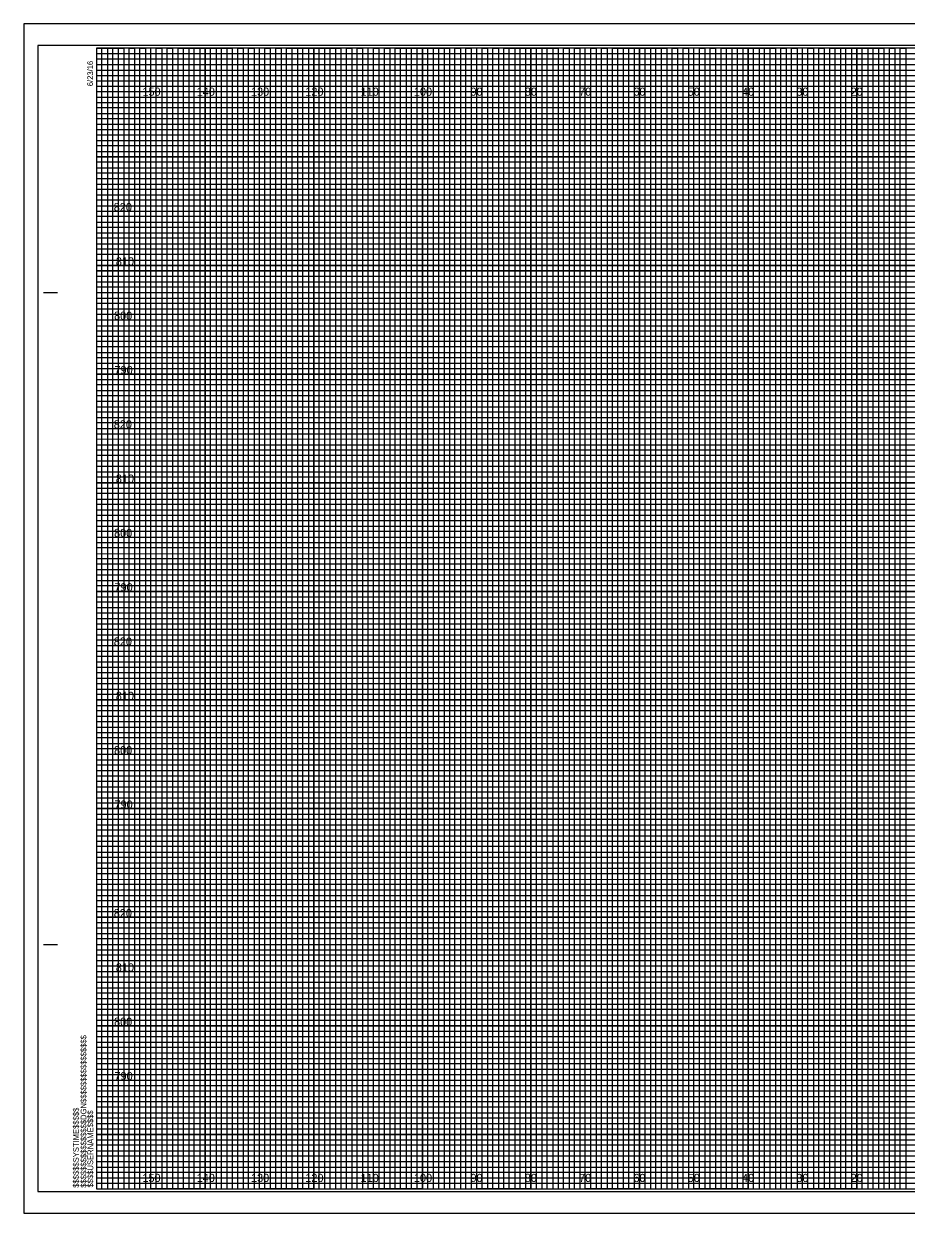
# Model space of a CAD drawing. Extents: x -13 to 323, y -4 to 214.
# Drawn here: x -13.4 to 149.1, y -4.5 to 214.5 of the extents above; entities that cross this region are included whole.
import ezdxf

# ---------------------------------------------------------------- set-up
doc = ezdxf.new("R2010")
doc.units = 0
for name, color, linetype in [('Exist Cross Section Cell', 7, 'Continuous'), ('Exist XS Ground Line', 7, 'Continuous'), ('Prop CMT Conc Surface', 7, 'Continuous'), ('Prop CMT Pvmt Course 1', 7, 'Continuous'), ('Prop CMT Pvmt Course 1 CG', 7, 'Continuous'), ('Prop CMT Pvmt Course 2', 7, 'Continuous'), ('Prop CMT Pvmt Course 3', 7, 'Continuous'), ('Prop CMT Pvmt Surface', 7, 'Continuous'), ('Prop CMT Subgrade Earthwork', 7, 'Continuous'), ('Scratch_Level_4', 7, 'Continuous'), ('Scratch_Level_7', 7, 'Continuous')]:
    doc.layers.add(name, color=color, linetype=linetype)

msp = doc.modelspace()

# ---------------------------------------------------------------- linework, layer by layer
at = {"layer": 'Exist XS Ground Line'}
for p, q in [((10, 210), (0, 210)), ((10, 0), (10, 210)), ((30, 210), (20, 210)), ((20, 210), (20, 0)), ((30, 0), (30, 210)), ((50, 210), (40, 210)), ((40, 210), (40, 0)), ((50, 0), (50, 210)), ((70, 210), (60, 210)), ((60, 210), (60, 0)), ((70, 0), (70, 210)), ((90, 210), (80, 210)), ((80, 210), (80, 0)), ((90, 0), (90, 210)), ((110, 210), (100, 210)), ((100, 210), (100, 0)), ((110, 0), (110, 210)), ((130, 210), (120, 210)), ((120, 210), (120, 0)), ((130, 0), (130, 210)), ((150, 210), (140, 210)), ((140, 210), (140, 0)), ((20, 0), (10, 0)), ((40, 0), (30, 0)), ((60, 0), (50, 0)), ((80, 0), (70, 0)), ((100, 0), (90, 0)), ((120, 0), (110, 0)), ((140, 0), (130, 0))]:
    msp.add_line(p, q, dxfattribs=at)
for points in [[(0, 200), (320, 200), (320, 190), (0, 190)], [(0, 180), (320, 180), (320, 170), (0, 170)], [(0, 160), (320, 160), (320, 150), (0, 150)], [(0, 140), (320, 140), (320, 130), (0, 130)], [(0, 120), (320, 120), (320, 110), (0, 110)], [(0, 100), (320, 100), (320, 90), (0, 90)], [(0, 80), (320, 80), (320, 70), (0, 70)], [(0, 60), (320, 60), (320, 50), (0, 50)], [(0, 40), (320, 40), (320, 30), (0, 30)], [(0, 20), (320, 20), (320, 10), (0, 10)]]:
    msp.add_lwpolyline(points, dxfattribs=at)
at = {"layer": 'Prop CMT Conc Surface'}
for p, q in [((323.3, 214.5), (-13.4, 214.5)), ((-13.4, 214.5), (-13.4, -4.5)), ((-13.4, -4.5), (323.3, -4.5))]:
    msp.add_line(p, q, dxfattribs=at)
at = {"layer": 'Prop CMT Pvmt Course 1'}
for p, q in [((10, 0), (10, 210)), ((20, 0), (20, 210)), ((30, 0), (30, 210)), ((40, 0), (40, 210)), ((50, 0), (50, 210)), ((60, 0), (60, 210)), ((70, 0), (70, 210)), ((80, 0), (80, 210)), ((90, 0), (90, 210)), ((100, 0), (100, 210)), ((110, 0), (110, 210)), ((120, 0), (120, 210)), ((130, 0), (130, 210)), ((140, 0), (140, 210)), ((0, 200), (320, 200)), ((0, 190), (320, 190)), ((0, 180), (320, 180)), ((0, 170), (320, 170)), ((0, 160), (320, 160)), ((0, 150), (320, 150)), ((0, 140), (320, 140)), ((0, 130), (320, 130)), ((0, 120), (320, 120)), ((0, 110), (320, 110)), ((0, 100), (320, 100)), ((0, 90), (320, 90)), ((0, 80), (320, 80)), ((0, 70), (320, 70)), ((0, 60), (320, 60)), ((0, 50), (320, 50)), ((0, 40), (320, 40)), ((0, 30), (320, 30)), ((0, 20), (320, 20)), ((0, 10), (320, 10))]:
    msp.add_line(p, q, dxfattribs=at)
at = {"layer": 'Prop CMT Pvmt Course 1 CG'}
msp.add_lwpolyline([(-10.8, -0.5), (322.4, -0.5), (322.4, 210.5), (-10.8, 210.5)], close=True, dxfattribs=at)
at = {"layer": 'Prop CMT Pvmt Course 2'}
for p, q in [((-9.8, 165), (-7.3, 165)), ((-9.7, 165), (-7.2, 165)), ((-9.8, 45), (-7.3, 45)), ((-9.7, 45), (-7.2, 45)), ((0, 0), (0, 0)), ((0, 0), (0, 0)), ((0, 0), (0, 0)), ((0, 0), (0, 0)), ((0, 0), (0, 0)), ((0, 0), (0, 0)), ((0, 0), (0, 0))]:
    msp.add_line(p, q, dxfattribs=at)
msp.add_lwpolyline([(320, 210), (0, 210), (0, 0), (320, 0)], close=True, dxfattribs=at)
at = {"layer": 'Prop CMT Pvmt Course 3'}
for points in [[(0, 0), (1, 0), (1, 210), (2, 210), (2, 0)], [(2, 0), (3, 0), (3, 210), (4, 210), (4, 0)], [(5, 0), (6, 0), (6, 210), (7, 210), (7, 0)], [(7, 0), (8, 0), (8, 210), (9, 210), (9, 0)], [(10, 0), (11, 0), (11, 210), (12, 210), (12, 0)], [(12, 0), (13, 0), (13, 210), (14, 210), (14, 0)], [(15, 0), (16, 0), (16, 210), (17, 210), (17, 0)], [(17, 0), (18, 0), (18, 210), (19, 210), (19, 0)], [(20, 0), (21, 0), (21, 210), (22, 210), (22, 0)], [(22, 0), (23, 0), (23, 210), (24, 210), (24, 0)], [(25, 0), (26, 0), (26, 210), (27, 210), (27, 0)], [(27, 0), (28, 0), (28, 210), (29, 210), (29, 0)], [(30, 0), (31, 0), (31, 210), (32, 210), (32, 0)], [(32, 0), (33, 0), (33, 210), (34, 210), (34, 0)], [(35, 0), (36, 0), (36, 210), (37, 210), (37, 0)], [(37, 0), (38, 0), (38, 210), (39, 210), (39, 0)], [(40, 0), (41, 0), (41, 210), (42, 210), (42, 0)], [(42, 0), (43, 0), (43, 210), (44, 210), (44, 0)], [(45, 0), (46, 0), (46, 210), (47, 210), (47, 0)], [(47, 0), (48, 0), (48, 210), (49, 210), (49, 0)], [(50, 0), (51, 0), (51, 210), (52, 210), (52, 0)], [(52, 0), (53, 0), (53, 210), (54, 210), (54, 0)], [(55, 0), (56, 0), (56, 210), (57, 210), (57, 0)], [(57, 0), (58, 0), (58, 210), (59, 210), (59, 0)], [(60, 0), (61, 0), (61, 210), (62, 210), (62, 0)], [(62, 0), (63, 0), (63, 210), (64, 210), (64, 0)], [(65, 0), (66, 0), (66, 210), (67, 210), (67, 0)], [(67, 0), (68, 0), (68, 210), (69, 210), (69, 0)], [(70, 0), (71, 0), (71, 210), (72, 210), (72, 0)], [(72, 0), (73, 0), (73, 210), (74, 210), (74, 0)], [(75, 0), (76, 0), (76, 210), (77, 210), (77, 0)], [(77, 0), (78, 0), (78, 210), (79, 210), (79, 0)], [(80, 0), (81, 0), (81, 210), (82, 210), (82, 0)], [(82, 0), (83, 0), (83, 210), (84, 210), (84, 0)], [(85, 0), (86, 0), (86, 210), (87, 210), (87, 0)], [(87, 0), (88, 0), (88, 210), (89, 210), (89, 0)], [(90, 0), (91, 0), (91, 210), (92, 210), (92, 0)], [(92, 0), (93, 0), (93, 210), (94, 210), (94, 0)], [(95, 0), (96, 0), (96, 210), (97, 210), (97, 0)], [(97, 0), (98, 0), (98, 210), (99, 210), (99, 0)], [(100, 0), (101, 0), (101, 210), (102, 210), (102, 0)], [(102, 0), (103, 0), (103, 210), (104, 210), (104, 0)], [(105, 0), (106, 0), (106, 210), (107, 210), (107, 0)], [(107, 0), (108, 0), (108, 210), (109, 210), (109, 0)], [(110, 0), (111, 0), (111, 210), (112, 210), (112, 0)], [(112, 0), (113, 0), (113, 210), (114, 210), (114, 0)], [(115, 0), (116, 0), (116, 210), (117, 210), (117, 0)], [(117, 0), (118, 0), (118, 210), (119, 210), (119, 0)], [(120, 0), (121, 0), (121, 210), (122, 210), (122, 0)], [(122, 0), (123, 0), (123, 210), (124, 210), (124, 0)], [(125, 0), (126, 0), (126, 210), (127, 210), (127, 0)], [(127, 0), (128, 0), (128, 210), (129, 210), (129, 0)], [(130, 0), (131, 0), (131, 210), (132, 210), (132, 0)], [(132, 0), (133, 0), (133, 210), (134, 210), (134, 0)], [(135, 0), (136, 0), (136, 210), (137, 210), (137, 0)], [(137, 0), (138, 0), (138, 210), (139, 210), (139, 0)], [(140, 0), (141, 0), (141, 210), (142, 210), (142, 0)], [(142, 0), (143, 0), (143, 210), (144, 210), (144, 0)], [(145, 0), (146, 0), (146, 210), (147, 210), (147, 0)], [(147, 0), (148, 0), (148, 210), (149, 210), (149, 0)]]:
    msp.add_lwpolyline(points, dxfattribs=at)
at = {"layer": 'Prop CMT Pvmt Surface'}
msp.add_lwpolyline([(-13.4, -4.5), (323.3, -4.5), (323.3, 214.5), (-13.4, 214.5)], close=True, dxfattribs=at)
at = {"layer": 'Scratch_Level_4'}
for points in [[(0, 210), (5, 210), (5, 0), (15, 0), (15, 210), (25, 210), (25, 0), (35, 0), (35, 210), (45, 210), (45, 0), (55, 0), (55, 210), (65, 210), (65, 0), (75, 0), (75, 210), (85, 210), (85, 0), (95, 0), (95, 210), (105, 210), (105, 0), (115, 0), (115, 210), (125, 210), (125, 0), (135, 0), (135, 210), (145, 210), (145, 0), (155, 0)], [(0, 205), (275, 205)], [(0, 185), (320, 185), (320, 195), (0, 195)], [(0, 165), (320, 165), (320, 175), (0, 175)], [(0, 145), (320, 145), (320, 155), (0, 155)], [(0, 125), (320, 125), (320, 135), (0, 135)], [(0, 105), (320, 105), (320, 115), (0, 115)], [(0, 85), (320, 85), (320, 95), (0, 95)], [(0, 65), (320, 65), (320, 75), (0, 75)], [(0, 45), (320, 45), (320, 55), (0, 55)], [(0, 25), (320, 25), (320, 35), (0, 35)], [(0, 5), (320, 5), (320, 15), (0, 15)]]:
    msp.add_lwpolyline(points, dxfattribs=at)
at = {"layer": 'Scratch_Level_7'}
for p, q in [((0, 209), (260, 209)), ((260, 207.98), (0, 207.98)), ((0, 207.98), (0, 207)), ((0, 207), (260, 207)), ((260, 205.89), (0, 205.89)), ((0, 205.89), (0, 204)), ((0, 204), (320, 204))]:
    msp.add_line(p, q, dxfattribs=at)
for points in [[(0, 203), (270, 203), (320, 203), (320, 202), (0, 202)], [(0, 201), (320, 201), (320, 199), (0, 199)], [(0, 198), (320, 198), (320, 197), (0, 196.98)], [(0, 196), (320, 196), (320, 194), (0, 194)], [(0, 193), (320, 193), (320, 192), (0, 192)], [(0, 191), (320, 191), (320, 189), (0, 189)], [(0, 188), (320, 188), (320, 187), (0, 187)], [(0, 186), (320, 186), (320, 184), (0, 184)], [(0, 183), (320, 183), (320, 182), (0, 182)], [(0, 181), (320, 181), (320, 179), (0, 179)], [(0, 178), (320, 178), (320, 177), (0, 177)], [(0, 176), (320, 176), (320, 173.95), (320, 173), (320, 172), (0, 172)], [(0, 174), (320, 174), (320, 173), (0, 173)], [(0, 171), (320, 171), (320, 169), (0, 169.03)], [(0, 169.03), (320, 169), (320, 168), (0, 168)], [(0, 167), (320, 167), (320, 166), (0, 166)], [(0, 164), (320, 164), (320, 163), (0, 163)], [(0, 162), (320, 162), (320, 161), (0, 161)], [(-0.07, 158.89), (320, 158.89), (320, 157.88), (-0.07, 157.88)], [(0, 157), (320, 157), (320, 156), (0, 156)], [(0, 154), (320, 154), (320, 153), (0, 153)], [(0, 152), (320, 152), (320, 151), (0, 151)], [(0, 149), (320, 149), (320, 148), (0, 148)], [(0, 147), (320, 147), (320, 146), (0, 146)], [(0, 144), (320, 144), (320, 143), (0, 143)], [(0, 142), (320, 142), (320, 141), (0, 141)], [(0, 139), (320, 139), (319.99, 137.98), (0, 138)], [(0, 137), (320, 137), (320, 136), (0, 136)], [(0, 134), (320, 134), (320, 133), (0, 133)], [(0, 132), (320, 132), (320, 131), (0, 131)], [(0, 129), (320, 129), (320, 128), (0, 128)], [(0, 127), (320, 127), (320, 126), (0, 126)], [(0, 124), (320, 124), (320, 123), (0, 123)], [(0, 122), (320, 122), (320, 121), (0, 121)], [(0, 119), (320, 119), (320, 118), (0, 118)], [(0, 116.99), (320.07, 116.91), (320, 116), (0, 116)], [(0, 114), (320, 114), (320, 113), (0, 113)], [(0, 112), (320, 112), (320, 111), (0, 111)], [(0, 109), (320, 109), (320, 108), (0, 108)], [(0, 107), (320, 107), (320, 106), (0, 106)], [(0, 104), (320, 104), (320, 103), (0, 103)], [(0, 102), (320, 102), (320, 101), (0, 101)], [(0, 99), (320, 99), (320, 98), (0, 98)], [(0, 97), (320, 97), (320, 96), (0, 96)], [(0, 94), (320, 94), (320, 93), (0, 93)], [(0, 92), (320, 92), (320, 91), (0, 91)], [(0, 89), (320, 89), (320, 88), (0, 88)], [(0, 87), (320, 87), (320, 86), (0, 86)], [(0, 84), (320, 84), (320, 83), (0, 83)], [(0, 82), (320, 82), (320, 81), (0, 81)], [(0, 79), (320, 79), (319.99, 77.98), (0, 78)], [(0, 77), (320, 77), (320, 76), (0, 76)], [(0, 74), (320, 74), (320, 73), (0, 73)], [(0, 72), (320, 72), (320, 71), (0, 71)], [(0, 69), (320, 69), (320, 68), (0, 68)], [(0, 67), (320, 67), (320, 66), (0, 66)], [(0, 64), (320, 64), (320, 63), (0, 63)], [(0, 62), (320, 62), (320, 61), (0, 61)], [(0, 59), (320, 59), (320, 58), (0, 58)], [(0, 56.99), (320.07, 56.91), (320, 56), (0, 56)], [(0, 54), (320, 54), (320, 53), (0, 53)], [(0, 52), (320, 52), (320, 51), (0, 51)], [(0, 49), (320, 49), (320, 48), (0, 48)], [(0, 47), (320, 47), (320, 46), (0, 46)], [(0, 44), (320, 44), (320, 43), (0, 43)], [(0, 42), (320, 42), (320, 41), (0, 41)], [(0, 39), (320, 39), (320, 38), (0, 38)], [(0, 37), (320, 37), (320, 36), (0, 36)], [(0, 34), (320, 34), (320, 33), (0, 33)], [(0, 32), (320, 32), (320, 31), (0, 31)], [(0, 29), (320, 29), (320, 28), (0, 28)], [(0, 27), (320, 27), (320, 26), (0, 26)], [(0, 24), (320, 24), (320, 23), (0, 23)], [(0, 22), (320, 22), (320, 21), (0, 21)], [(0, 19), (320, 19), (320, 18), (0, 18)], [(0, 17), (320, 17), (320, 16), (0, 16)], [(0, 14), (320, 14), (320, 13), (0, 13)], [(0, 12), (320, 12), (320, 11), (0, 11)], [(0, 9), (320, 9), (320, 8), (0, 8)], [(0, 7), (320, 7), (320, 6), (0, 6)], [(0, 4), (320, 4), (320, 3), (0, 3)], [(0, 2), (320, 2), (320, 1), (0, 1)]]:
    msp.add_lwpolyline(points, dxfattribs=at)

# ---------------------------------------------------------------- texts
at = {"layer": 'Exist Cross Section Cell'}
for s, p in [('150', (8.44, 201.25)), ('140', (18.44, 201.25)), ('130', (28.44, 201.25)), ('120', (38.44, 201.25)), ('110', (48.62, 201.25)), ('100', (58.44, 201.25)), ('90', (68.86, 201.25)), ('80', (78.86, 201.25)), ('70', (88.86, 201.25)), ('60', (98.86, 201.25)), ('50', (108.86, 201.25)), ('40', (118.86, 201.25)), ('30', (128.86, 201.25)), ('20', (138.86, 201.25)), ('150', (8.44, 1.25)), ('140', (18.44, 1.25)), ('130', (28.44, 1.25)), ('120', (38.44, 1.25)), ('110', (48.62, 1.25)), ('100', (58.44, 1.25)), ('90', (68.86, 1.25)), ('80', (78.86, 1.25)), ('70', (88.86, 1.25)), ('60', (98.86, 1.25)), ('50', (108.86, 1.25)), ('40', (118.86, 1.25)), ('30', (128.86, 1.25)), ('20', (138.86, 1.25))]:
    msp.add_text(s, height=1.5, dxfattribs=at).set_placement(p)
at = {"layer": 'Prop CMT Pvmt Course 2'}
for s, p in [('6/23/16', (-0.65, 203)), ('$$$$$$$$$$$$$$$$DGN$$$$$$$$$$$$$$$$', (-1.88, 0.18)), ('$$$$$$SYSTIME$$$$$', (-3.26, 0.18)), ('$$$$USERNAME$$$$', (-0.62, 0.23))]:
    msp.add_text(s, height=1.05, rotation=90, dxfattribs=at).set_placement(p)
at = {"layer": 'Prop CMT Subgrade Earthwork'}
for s, p in [('820', (3.17, 180)), ('810', (3.55, 170)), ('800', (3.22, 160)), ('790', (3.3, 150)), ('820', (3.17, 140)), ('810', (3.55, 130)), ('800', (3.22, 120)), ('790', (3.3, 110)), ('820', (3.17, 100)), ('810', (3.55, 90)), ('800', (3.22, 80)), ('790', (3.3, 70)), ('820', (3.17, 50)), ('810', (3.55, 40)), ('800', (3.22, 30)), ('790', (3.3, 20))]:
    msp.add_text(s, height=1.5, dxfattribs=at).set_placement(p)

doc.saveas('drawing.dxf')
